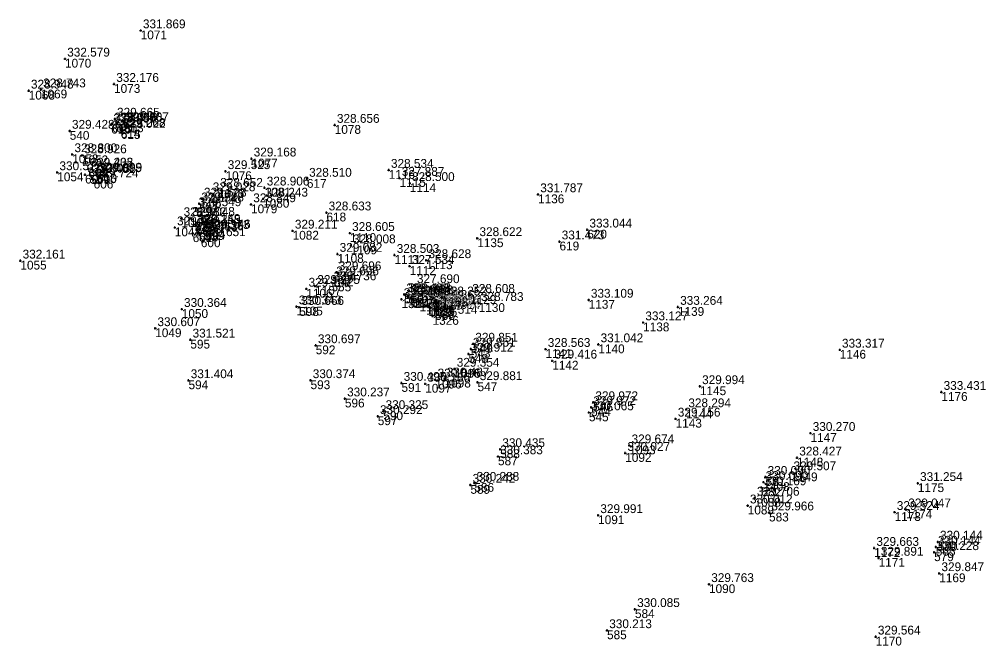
# Model space of a CAD drawing. Extents: x -829398 to -819400, y -1074439 to -1067977.
# Drawn here: x -824049.1 to -823917.6, y -1072558.2 to -1072473 of the extents above; entities that cross this region are included whole.
import ezdxf

# ---------------------------------------------------------------- set-up
doc = ezdxf.new("R2010")
doc.units = 0
for name, color, linetype in [('Vrstva 60', 7, 'Continuous'), ('Vrstva 61', 7, 'Continuous'), ('Čísla bodů_doměření_2012', 7, 'Continuous')]:
    doc.layers.add(name, color=color, linetype=linetype)

# ---------------------------------------------------------------- blocks, each defined once
blk = doc.blocks.new('BOD')
at = {"layer": 'Čísla bodů_doměření_2012'}
for p, q in [((-0.15, 0), (0.15, 0)), ((0, -0.15), (0, 0.15))]:
    blk.add_line(p, q, dxfattribs=at)

msp = doc.modelspace()

# ---------------------------------------------------------------- block references
at = {"layer": 'Vrstva 60'}
for p in [(-824032.551, -1072474.557), (-824042.851, -1072478.403), (-824047.787, -1072482.751), (-824046.128, -1072482.589), (-824036.176, -1072481.841), (-824036.068, -1072486.573), (-824042.206, -1072488.217), (-824036.57, -1072487.377), (-824036.432, -1072487.222), (-824035.705, -1072487.257), (-824035.277, -1072487.984), (-824035.251, -1072488.091), (-824034.835, -1072487.185), (-824006.151, -1072487.409), (-824041.862, -1072491.4), (-824040.554, -1072491.551), (-824017.476, -1072491.986), (-824039.683, -1072493.366), (-824039.664, -1072493.376), (-824043.907, -1072493.851), (-824040.123, -1072494.168), (-824039.416, -1072494.224), (-824038.502, -1072494.114), (-824038.458, -1072494.054), (-824021.008, -1072493.703), (-824009.937, -1072494.747), (-823998.802, -1072493.527), (-823997.332, -1072494.628), (-824038.953, -1072494.838), (-824022.03, -1072496.112), (-824015.7, -1072495.933), (-823995.936, -1072495.328), (-824024.242, -1072497.445), (-824023.045, -1072496.718), (-824015.891, -1072497.45), (-823978.483, -1072496.849), (-824024.965, -1072498.744), (-824024.606, -1072498.098), (-824017.538, -1072498.206), (-824025.842, -1072500.065), (-824007.277, -1072499.321), (-824027.907, -1072501.34), (-824027.012, -1072500.104), (-824025.078, -1072501.029), (-824025.051, -1072501.132), (-824025.475, -1072502.131), (-824024.645, -1072502.024), (-824023.835, -1072501.84), (-824023.694, -1072501.766), (-824011.877, -1072501.799), (-824004.086, -1072502.114), (-823971.793, -1072501.647), (-824024.367, -1072502.822), (-824003.965, -1072503.794), (-823986.757, -1072502.816), (-823975.566, -1072503.262), (-824005.774, -1072504.95), (-823998.014, -1072505.098), (-824048.918, -1072505.864), (-823995.957, -1072506.601), (-823993.689, -1072505.81), (-824005.905, -1072507.449), (-824006.593, -1072508.822), (-824006.249, -1072508.149), (-823995.266, -1072509.209), (-824010.015, -1072509.693), (-824008.819, -1072509.318), (-823996.707, -1072510.447), (-823996.452, -1072510.432), (-823987.741, -1072510.531), (-823997.062, -1072511.108), (-823996.116, -1072510.726), (-823995.814, -1072510.895), (-823995.505, -1072511.048), (-823995.473, -1072511.064), (-823994.609, -1072511.546), (-823992.433, -1072511.361), (-823991.551, -1072510.881), (-823986.563, -1072511.635), (-823971.597, -1072511.193), (-824026.958, -1072512.444), (-824011.344, -1072512.098), (-824010.981, -1072512.173), (-823993.718, -1072511.994), (-823993.651, -1072512.021), (-823993.388, -1072512.172), (-823993.054, -1072512.242), (-823992.56, -1072512.48), (-823992.481, -1072512.716), (-823959.451, -1072512.157), (-823992.836, -1072513.377), (-823964.186, -1072514.266), (-824030.572, -1072515.057), (-824025.794, -1072516.607), (-823987.321, -1072517.17), (-824008.74, -1072517.378), (-823987.638, -1072517.855), (-823977.464, -1072517.885), (-823970.276, -1072517.245), (-823937.431, -1072517.983), (-823987.952, -1072518.538), (-823976.552, -1072519.472), (-823989.847, -1072520.578), (-824026.044, -1072522.134), (-824009.44, -1072522.128), (-823992.45, -1072522.038), (-823991.206, -1072521.904), (-823986.72, -1072522.399), (-823997.07, -1072522.496), (-823993.836, -1072522.607), (-823956.463, -1072522.944), (-823923.603, -1072523.724), (-824004.766, -1072524.612), (-823999.534, -1072526.338), (-823971.259, -1072525.793), (-823970.982, -1072525.126), (-823958.338, -1072526.087), (-824000.293, -1072527.019), (-823971.563, -1072526.5), (-823959.767, -1072527.36), (-823941.411, -1072529.306), (-823983.645, -1072531.51), (-823966.063, -1072530.993), (-823983.935, -1072532.482), (-823966.623, -1072532.02), (-823943.244, -1072532.649), (-823947.548, -1072535.286), (-823944.025, -1072534.654), (-823987.69, -1072536.356), (-823987.146, -1072536.087), (-823948.081, -1072536.7), (-823947.812, -1072535.984), (-823926.807, -1072536.123), (-823949.013, -1072538.115), (-823949.954, -1072539.167), (-823970.31, -1072540.48), (-823947.051, -1072540.116), (-823929.972, -1072540.055), (-823928.417, -1072539.702), (-823924.367, -1072544.784), (-823924.09, -1072544.083), (-823932.75, -1072544.937), (-823924.594, -1072545.511), (-823932.148, -1072546.281), (-823923.895, -1072548.377), (-823955.223, -1072549.86), (-823965.3, -1072553.258), (-823969.1, -1072556.13), (-823932.547, -1072556.992)]:
    msp.add_blockref('BOD', p, dxfattribs=at)

# ---------------------------------------------------------------- texts
for s, p in [('1071', (-824032.551, -1072475.757)), ('1070', (-824042.851, -1072479.603)), ('1068', (-824047.787, -1072483.951)), ('1069', (-824046.128, -1072483.789)), ('1073', (-824036.176, -1072483.041)), ('612', (-824036.068, -1072487.773)), ('616', (-824036.57, -1072488.577)), ('611', (-824036.432, -1072488.422)), ('560', (-824035.705, -1072488.457)), ('614', (-824035.277, -1072489.184)), ('615', (-824035.251, -1072489.291)), ('613', (-824034.835, -1072488.385)), ('1078', (-824006.151, -1072488.609)), ('540', (-824042.206, -1072489.417)), ('1053', (-824041.862, -1072492.6)), ('1052', (-824040.554, -1072492.751)), ('1077', (-824017.476, -1072493.186)), ('608', (-824039.683, -1072494.566)), ('609', (-824039.664, -1072494.576)), ('1054', (-824043.907, -1072495.051)), ('607', (-824040.123, -1072495.368)), ('559', (-824039.416, -1072495.424)), ('605', (-824038.502, -1072495.314)), ('610', (-824038.458, -1072495.254)), ('1076', (-824021.008, -1072494.903)), ('1116', (-823998.802, -1072494.727)), ('1115', (-823997.332, -1072495.828)), ('606', (-824038.953, -1072496.038)), ('1081', (-824015.7, -1072497.133)), ('617', (-824009.937, -1072495.947)), ('1114', (-823995.936, -1072496.528)), ('1074', (-824023.045, -1072497.918)), ('1075', (-824022.03, -1072497.312)), ('1136', (-823978.483, -1072498.049)), ('541', (-824024.606, -1072499.298)), ('556', (-824024.242, -1072498.645)), ('1079', (-824017.538, -1072499.406)), ('1080', (-824015.891, -1072498.65)), ('557', (-824024.965, -1072499.944)), ('618', (-824007.277, -1072500.521)), ('1047', (-824027.012, -1072501.304)), ('1046', (-824025.842, -1072501.265)), ('603', (-824025.078, -1072502.229)), ('602', (-824025.051, -1072502.332)), ('1048', (-824027.907, -1072502.54)), ('601', (-824025.475, -1072503.331)), ('558', (-824024.645, -1072503.224)), ('599', (-824023.835, -1072503.04)), ('604', (-824023.694, -1072502.966)), ('1082', (-824011.877, -1072502.999)), ('1110', (-824004.086, -1072503.314)), ('620', (-823971.793, -1072502.847)), ('600', (-824024.367, -1072504.022)), ('1109', (-824003.965, -1072504.994)), ('1135', (-823986.757, -1072504.016)), ('619', (-823975.566, -1072504.462)), ('1108', (-824005.774, -1072506.15)), ('1111', (-823998.014, -1072506.298)), ('1055', (-824048.918, -1072507.064)), ('1113', (-823993.689, -1072507.01)), ('554', (-824005.905, -1072508.649)), ('1112', (-823995.957, -1072507.801)), ('555', (-824006.593, -1072510.022)), ('542', (-824006.249, -1072509.349)), ('1106', (-824010.015, -1072510.893)), ('1107', (-824008.819, -1072510.518)), ('552', (-823996.707, -1072511.647)), ('551', (-823996.452, -1072511.632)), ('1118', (-823995.266, -1072510.409)), ('1327', (-823997.062, -1072512.308)), ('1127', (-823996.116, -1072511.926)), ('1119', (-823995.814, -1072512.095)), ('1120', (-823995.505, -1072512.248)), ('1121', (-823995.473, -1072512.264)), ('1122', (-823994.609, -1072512.746)), ('1117', (-823992.433, -1072512.561)), ('1128', (-823991.551, -1072512.081)), ('1129', (-823987.741, -1072511.731)), ('1130', (-823986.563, -1072512.835)), ('1137', (-823971.597, -1072512.393)), ('1050', (-824026.958, -1072513.644)), ('1105', (-824011.344, -1072513.298)), ('598', (-824010.981, -1072513.373)), ('1124', (-823993.718, -1072513.194)), ('1123', (-823993.651, -1072513.221)), ('1125', (-823993.388, -1072513.372)), ('1126', (-823993.054, -1072513.442)), ('550', (-823992.56, -1072513.68)), ('553', (-823992.481, -1072513.916)), ('1139', (-823959.451, -1072513.357)), ('1326', (-823992.836, -1072514.577)), ('1138', (-823964.186, -1072515.466)), ('1049', (-824030.572, -1072516.257)), ('595', (-824025.794, -1072517.807)), ('592', (-824008.74, -1072518.578)), ('543', (-823987.638, -1072519.055)), ('549', (-823987.321, -1072518.37)), ('1141', (-823977.464, -1072519.085)), ('1140', (-823970.276, -1072518.445)), ('1146', (-823937.431, -1072519.183)), ('548', (-823987.952, -1072519.738)), ('1142', (-823976.552, -1072520.672)), ('1095', (-823989.847, -1072521.778)), ('594', (-824026.044, -1072523.334)), ('593', (-824009.44, -1072523.328)), ('1096', (-823992.45, -1072523.238)), ('1098', (-823991.206, -1072523.104)), ('591', (-823997.07, -1072523.696)), ('1097', (-823993.836, -1072523.807)), ('547', (-823986.72, -1072523.599)), ('1145', (-823956.463, -1072524.144)), ('596', (-824004.766, -1072525.812)), ('1176', (-823923.603, -1072524.924)), ('544', (-823971.259, -1072526.993)), ('546', (-823970.982, -1072526.326)), ('1144', (-823958.338, -1072527.287)), ('597', (-824000.293, -1072528.219)), ('590', (-823999.534, -1072527.538)), ('545', (-823971.563, -1072527.7)), ('1143', (-823959.767, -1072528.56)), ('1147', (-823941.411, -1072530.506)), ('588', (-823983.645, -1072532.71)), ('1093', (-823966.063, -1072532.193)), ('587', (-823983.935, -1072533.682)), ('1092', (-823966.623, -1072533.22)), ('1148', (-823943.244, -1072533.849)), ('581', (-823947.548, -1072536.486)), ('1149', (-823944.025, -1072535.854)), ('589', (-823987.69, -1072537.556)), ('586', (-823987.146, -1072537.287)), ('582', (-823948.081, -1072537.9)), ('1408', (-823947.812, -1072537.184)), ('1175', (-823926.807, -1072537.323)), ('1089', (-823949.954, -1072540.367)), ('1088', (-823949.013, -1072539.315)), ('1091', (-823970.31, -1072541.68)), ('583', (-823947.051, -1072541.316)), ('1173', (-823929.972, -1072541.255)), ('1174', (-823928.417, -1072540.902)), ('580', (-823924.09, -1072545.283)), ('1172', (-823932.75, -1072546.137)), ('579', (-823924.594, -1072546.711)), ('565', (-823924.367, -1072545.984)), ('1171', (-823932.148, -1072547.481)), ('1169', (-823923.895, -1072549.577)), ('1090', (-823955.223, -1072551.06)), ('584', (-823965.3, -1072554.458)), ('585', (-823969.1, -1072557.33)), ('1170', (-823932.547, -1072558.192))]:
    msp.add_text(s, height=1.2, dxfattribs=at).set_placement(p)
at = {"layer": 'Vrstva 61'}
for s, p in [('331.869', (-824032.251, -1072474.257)), ('332.579', (-824042.551, -1072478.103)), ('328.948', (-824047.487, -1072482.451)), ('328.743', (-824045.828, -1072482.289)), ('332.176', (-824035.876, -1072481.541)), ('329.665', (-824035.768, -1072486.273)), ('329.428', (-824041.906, -1072487.917)), ('328.997', (-824036.27, -1072487.077)), ('329.346', (-824036.132, -1072486.922)), ('329.366', (-824035.405, -1072486.957)), ('329.268', (-824034.977, -1072487.684)), ('329.022', (-824034.951, -1072487.791)), ('329.707', (-824034.535, -1072486.885)), ('328.656', (-824005.851, -1072487.109)), ('328.800', (-824041.562, -1072491.1)), ('328.926', (-824040.254, -1072491.251)), ('329.168', (-824017.176, -1072491.686)), ('329.432', (-824039.383, -1072493.066)), ('329.205', (-824039.364, -1072493.076)), ('328.534', (-823998.502, -1072493.227)), ('330.512', (-824043.607, -1072493.551)), ('329.805', (-824039.823, -1072493.868)), ('329.461', (-824039.116, -1072493.924)), ('329.724', (-824038.653, -1072494.538)), ('329.395', (-824038.202, -1072493.814)), ('329.099', (-824038.158, -1072493.754)), ('329.525', (-824020.708, -1072493.403)), ('328.510', (-824009.637, -1072494.447)), ('327.887', (-823997.032, -1072494.328)), ('328.652', (-824021.73, -1072495.812)), ('328.906', (-824015.4, -1072495.633)), ('328.500', (-823995.636, -1072495.028)), ('329.528', (-824023.942, -1072497.145)), ('329.028', (-824022.745, -1072496.418)), ('328.243', (-824015.591, -1072497.15)), ('331.787', (-823978.183, -1072496.549)), ('329.549', (-824024.665, -1072498.444)), ('329.528', (-824024.306, -1072497.798)), ('328.849', (-824017.238, -1072497.906)), ('328.982', (-824026.712, -1072499.804)), ('329.048', (-824025.542, -1072499.765)), ('328.633', (-824006.977, -1072499.021)), ('329.903', (-824027.607, -1072501.04)), ('329.149', (-824024.778, -1072500.729)), ('329.355', (-824024.751, -1072500.832)), ('329.663', (-824025.175, -1072501.831)), ('329.436', (-824024.345, -1072501.724)), ('329.373', (-824023.535, -1072501.54)), ('329.146', (-824023.394, -1072501.466)), ('329.211', (-824011.577, -1072501.499)), ('328.605', (-824003.786, -1072501.814)), ('333.044', (-823971.493, -1072501.347)), ('329.651', (-824024.067, -1072502.522)), ('328.008', (-824003.665, -1072503.494)), ('328.622', (-823986.457, -1072502.516)), ('331.473', (-823975.266, -1072502.962)), ('329.082', (-824005.474, -1072504.65)), ('328.503', (-823997.714, -1072504.798)), ('332.161', (-824048.618, -1072505.564)), ('327.534', (-823995.657, -1072506.301)), ('328.628', (-823993.389, -1072505.51)), ('329.696', (-824005.605, -1072507.149)), ('329.275', (-824008.519, -1072509.018)), ('329.736', (-824006.293, -1072508.522)), ('329.696', (-824005.949, -1072507.849)), ('327.690', (-823994.966, -1072508.909)), ('329.107', (-824009.715, -1072509.393)), ('329.408', (-823996.407, -1072510.147)), ('329.443', (-823996.152, -1072510.132)), ('328.608', (-823987.441, -1072510.231)), ('329.408', (-823996.762, -1072510.808)), ('329.008', (-823995.816, -1072510.426)), ('327.501', (-823995.514, -1072510.595)), ('327.489', (-823995.205, -1072510.748)), ('328.048', (-823995.173, -1072510.764)), ('328.439', (-823994.309, -1072511.246)), ('327.862', (-823992.133, -1072511.061)), ('328.252', (-823991.251, -1072510.581)), ('328.783', (-823986.263, -1072511.335)), ('333.109', (-823971.297, -1072510.893)), ('330.364', (-824026.658, -1072512.144)), ('330.343', (-824011.044, -1072511.798)), ('330.666', (-824010.681, -1072511.873)), ('327.430', (-823993.418, -1072511.694)), ('328.098', (-823993.351, -1072511.721)), ('327.581', (-823993.088, -1072511.872)), ('328.917', (-823992.754, -1072511.942)), ('329.546', (-823992.26, -1072512.18)), ('329.514', (-823992.181, -1072512.416)), ('333.264', (-823959.151, -1072511.857)), ('329.514', (-823992.536, -1072513.077)), ('333.127', (-823963.886, -1072513.966)), ('330.607', (-824030.272, -1072514.757)), ('331.521', (-824025.494, -1072516.307)), ('329.851', (-823987.021, -1072516.87)), ('330.697', (-824008.44, -1072517.078)), ('329.912', (-823987.652, -1072518.238)), ('329.851', (-823987.338, -1072517.555)), ('328.563', (-823977.164, -1072517.585)), ('331.042', (-823969.976, -1072516.945)), ('333.317', (-823937.131, -1072517.683)), ('329.416', (-823976.252, -1072519.172)), ('329.354', (-823989.547, -1072520.278)), ('331.404', (-824025.744, -1072521.834)), ('330.374', (-824009.14, -1072521.828)), ('330.516', (-823992.15, -1072521.738)), ('330.487', (-823990.906, -1072521.604)), ('329.881', (-823986.42, -1072522.099)), ('330.495', (-823996.77, -1072522.196)), ('330.186', (-823993.536, -1072522.307)), ('329.994', (-823956.163, -1072522.644)), ('333.431', (-823923.303, -1072523.424)), ('330.237', (-824004.466, -1072524.312)), ('330.325', (-823999.234, -1072526.038)), ('329.972', (-823970.959, -1072525.493)), ('329.972', (-823970.682, -1072524.826)), ('328.294', (-823958.038, -1072525.787)), ('330.292', (-823999.993, -1072526.719)), ('330.065', (-823971.263, -1072526.2)), ('329.156', (-823959.467, -1072527.06)), ('330.270', (-823941.111, -1072529.006)), ('330.435', (-823983.345, -1072531.21)), ('329.674', (-823965.763, -1072530.693)), ('330.383', (-823983.635, -1072532.182)), ('330.027', (-823966.323, -1072531.72)), ('328.427', (-823942.944, -1072532.349)), ('330.090', (-823947.248, -1072534.986)), ('329.507', (-823943.725, -1072534.354)), ('330.242', (-823987.39, -1072536.056)), ('330.288', (-823986.846, -1072535.787)), ('330.169', (-823947.781, -1072536.4)), ('330.090', (-823947.512, -1072535.684)), ('331.254', (-823926.507, -1072535.823)), ('329.706', (-823948.713, -1072537.815)), ('330.012', (-823949.654, -1072538.867)), ('329.991', (-823970.01, -1072540.18)), ('329.966', (-823946.751, -1072539.816)), ('329.524', (-823929.672, -1072539.755)), ('329.047', (-823928.117, -1072539.402)), ('330.144', (-823924.067, -1072544.484)), ('330.144', (-823923.79, -1072543.783)), ('329.663', (-823932.45, -1072544.637)), ('330.228', (-823924.294, -1072545.211)), ('329.891', (-823931.848, -1072545.981)), ('329.847', (-823923.595, -1072548.077)), ('329.763', (-823954.923, -1072549.56)), ('330.085', (-823965, -1072552.958)), ('330.213', (-823968.8, -1072555.83)), ('329.564', (-823932.247, -1072556.692))]:
    msp.add_text(s, height=1.2, dxfattribs=at).set_placement(p)

doc.saveas('drawing.dxf')
